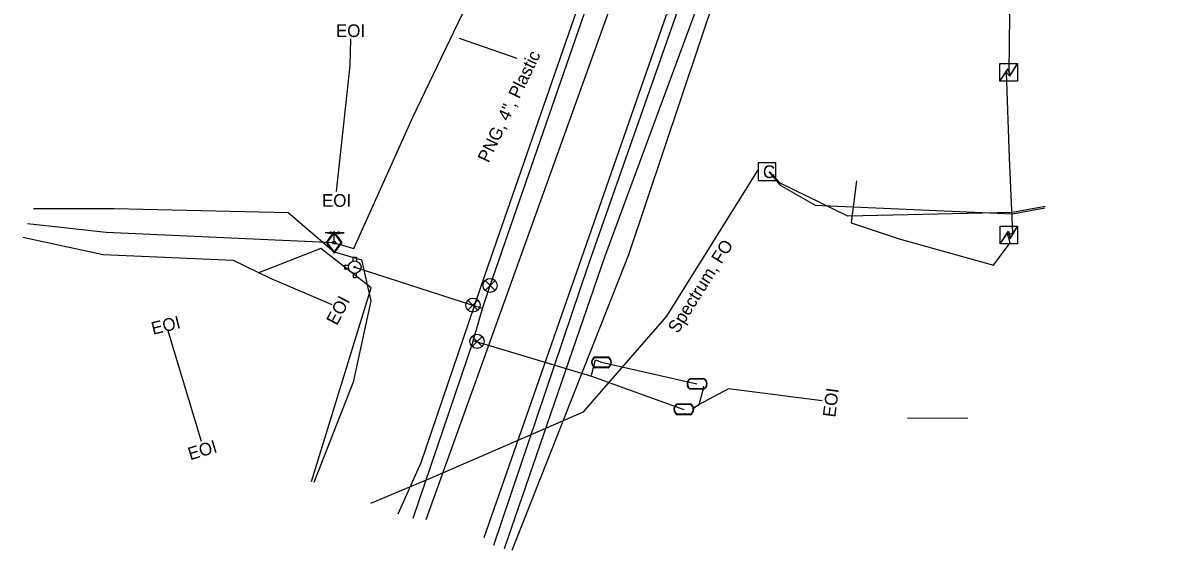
# Model space of a CAD drawing. Extents: x 2070721 to 2083039, y 729290 to 737883.
# Drawn here: x 2080826 to 2081187.2, y 732787 to 732953.4 of the extents above; entities that cross this region are included whole.
import ezdxf

# ---------------------------------------------------------------- set-up
doc = ezdxf.new("R2010")
doc.units = 0
for name, color, linetype in [('Cogo Default Point CELL', 7, 'Continuous'), ('COGO Default Point Elevation', 7, 'Continuous'), ('COGO Default Point Number', 7, 'Continuous'), ('Exist Utilities Gas UG Line SUE LOS B Cogo Point CELL', 7, 'Continuous'), ('Exist Utilities Gas Valve Cogo Number', 7, 'Continuous'), ('Exist Utilities Power UG Cable SUE LOS B Cogo Comment', 7, 'Continuous'), ('Exist Utilities Telephone UG Cable SUE LOS C Cogo Comment', 7, 'Continuous'), ('Exist Utilities Telephone UG Cable SUE LOS C Cogo Number', 7, 'Continuous'), ('Exist Utilities Telephone UG FO Cogo Point CELL', 7, 'Continuous'), ('Exist Utilities Telephone UG FO SUE LOS B Cogo Point CELL', 7, 'Continuous'), ('Exist Utilities TV Pedestal CELL', 7, 'Continuous'), ('Exist Utilities TV Pedestal Cogo Elevation', 7, 'Continuous'), ('Exist Utilities TV Pedestal Cogo Number', 7, 'Continuous'), ('Exist Utilities TV UG Cable Cogo Point CELL', 7, 'Continuous'), ('Exist Utilities TV UG Cable SUE LOS C Cogo Comment', 7, 'Continuous'), ('Exist Utilities TV UG Cable SUE LOS C Cogo Elevation', 7, 'Continuous'), ('Exist Utilities TV UG Cable SUE LOS C Cogo Number', 7, 'Continuous'), ('Exist Utilities TV UG Cable SUE LOS C Cogo Point CELL', 7, 'Continuous'), ('Exist Utilities TV UG FO Cable SUE Cogo Point CELL', 7, 'Continuous'), ('Exist Utilities TV UG FO Cable SUE LOS B Cogo Comment', 7, 'Continuous'), ('Exist Utilities TV UG FO Cable SUE LOS B Cogo Elevation', 7, 'Continuous'), ('Exist Utilities Water Meter Cogo Elevation', 7, 'Continuous')]:
    doc.layers.add(name, color=color, linetype=linetype)

msp = doc.modelspace()

# ---------------------------------------------------------------- linework, layer by layer
at = {"layer": 'Cogo Default Point CELL'}
msp.add_line((2081060.69, 732906.43), (2081060.69, 732906.43), dxfattribs=at)
msp.add_lwpolyline([(2081057.92, 732903.65), (2081063.47, 732903.65), (2081063.47, 732909.2), (2081057.92, 732909.2), (2081057.92, 732903.65)], dxfattribs=at)
at = {"layer": 'COGO Default Point Elevation'}
for points in [[(2080974.93, 732872.11), (2080971.78, 732868.96), (2080973.35, 732870.54), (2080974.93, 732868.96), (2080971.78, 732872.11)], [(2080969.51, 732865.91), (2080966.36, 732862.76), (2080967.94, 732864.33), (2080969.51, 732862.76), (2080966.36, 732865.91)], [(2080970.81, 732854.48), (2080967.66, 732851.33), (2080969.23, 732852.91), (2080970.81, 732851.33), (2080967.66, 732854.48)]]:
    msp.add_lwpolyline(points, dxfattribs=at)
for centre in [(2080973.35, 732870.54), (2080967.94, 732864.33), (2080969.23, 732852.91)]:
    msp.add_circle(centre, 2.23, dxfattribs=at)
at = {"layer": 'COGO Default Point Number'}
msp.add_line((2080930.67, 732876.3), (2080930.67, 732876.3), dxfattribs=at)
for points in [[(2080930.15, 732878.21), (2080930.15, 732879.5), (2080931.18, 732879.5), (2080931.18, 732878.18)], [(2080928.75, 732876.81), (2080927.47, 732876.81), (2080927.47, 732875.78), (2080928.75, 732875.78)], [(2080930.15, 732874.38), (2080930.15, 732873.1), (2080931.18, 732873.1), (2080931.18, 732874.41)]]:
    msp.add_lwpolyline(points, dxfattribs=at)
for radius in [1.98, 0.243]:
    msp.add_circle((2080930.67, 732876.3), radius, dxfattribs=at)
at = {"layer": 'Exist Utilities Gas Valve Cogo Number'}
msp.add_line((2080963.56, 732948.59), (2080981.81, 732942.29), dxfattribs=at)
at = {"layer": 'Exist Utilities Power UG Cable SUE LOS B Cogo Comment'}
for p, q in [((2080927.31, 732887.13), (2080921.34, 732887.13)), ((2080924.17, 732884.04), (2080924.17, 732887.13)), ((2080924.17, 732887.13), (2080927.31, 732887.13)), ((2080924.17, 732884.04), (2080924.17, 732884.04))]:
    msp.add_line(p, q, dxfattribs=at)
for points in [[(2080921.34, 732887.13), (2080923.32, 732887.47), (2080922.9, 732887.13), (2080923.28, 732886.82)], [(2080927.31, 732887.13), (2080925.34, 732886.78), (2080925.76, 732887.13), (2080925.37, 732887.43)]]:
    msp.add_lwpolyline(points, close=True, dxfattribs=at)
msp.add_circle((2080924.17, 732884.04), 0.517, dxfattribs=at)
at = {"layer": 'Exist Utilities Telephone UG Cable SUE LOS C Cogo Comment'}
for points in [[(2080929.29, 732948.39), (2080929.09, 732939.96), (2080924.86, 732900.17)], [(2080826.03, 732885.74), (2080851.32, 732880.36), (2080892.32, 732878.51), (2080903.75, 732872.9), (2080923.44, 732864.52)], [(2080882.35, 732821.33), (2080871.74, 732856.59)]]:
    msp.add_lwpolyline(points, dxfattribs=at)
at = {"layer": 'Exist Utilities Telephone UG Cable SUE LOS C Cogo Number'}
for p, q in [((2081136.91, 732937.96), (2081136.91, 732937.96)), ((2081137, 732886.66), (2081137, 732886.66))]:
    msp.add_line(p, q, dxfattribs=at)
for points in [[(2081134.06, 732940.57), (2081139.61, 732940.57), (2081139.61, 732935.02), (2081134.06, 732935.02)], [(2081134.16, 732889.27), (2081139.71, 732889.27), (2081139.71, 732883.72), (2081134.16, 732883.72)]]:
    msp.add_lwpolyline(points, close=True, dxfattribs=at)
for points in [[(2081134.06, 732935.02), (2081136.71, 732938.96), (2081137.34, 732936.75), (2081139.61, 732940.57)], [(2081134.13, 732935.02), (2081136.71, 732938.75), (2081137.29, 732936.57), (2081139.61, 732940.42)], [(2081134.16, 732883.72), (2081136.8, 732887.66), (2081137.43, 732885.45), (2081139.71, 732889.27)], [(2081134.23, 732883.72), (2081136.8, 732887.45), (2081137.39, 732885.27), (2081139.71, 732889.12)]]:
    msp.add_lwpolyline(points, dxfattribs=at)
at = {"layer": 'Exist Utilities Telephone UG FO Cogo Point CELL'}
for p, q in [((2081008.49, 732846.29), (2081008.49, 732846.29)), ((2081038.62, 732839.51), (2081038.62, 732839.51)), ((2081034.46, 732831.47), (2081034.46, 732831.47))]:
    msp.add_line(p, q, dxfattribs=at)
for points in [[(2081006.45, 732847.99), (2081010.53, 732847.99)], [(2081006.45, 732847.86), (2081010.53, 732847.86)], [(2081010.53, 732844.73), (2081006.43, 732844.73)], [(2081010.53, 732844.59), (2081006.43, 732844.59)], [(2081040.65, 732837.95), (2081036.55, 732837.95)], [(2081036.58, 732841.21), (2081040.65, 732841.21)], [(2081036.58, 732841.08), (2081040.65, 732841.08)], [(2081040.65, 732837.81), (2081036.55, 732837.81)], [(2081032.42, 732833.17), (2081036.49, 732833.17)], [(2081032.42, 732833.04), (2081036.49, 732833.04)], [(2081036.49, 732829.91), (2081032.39, 732829.91)], [(2081036.49, 732829.77), (2081032.39, 732829.77)]]:
    msp.add_lwpolyline(points, dxfattribs=at)
for centre, radius, start, end in [((2081007.18, 732846.29), 1.86, 113.178, 245.9794), ((2081007.19, 732846.29), 1.73, 115.3009, 243.7824), ((2081009.78, 732846.3), 1.86, 293.6483, 66.3084), ((2081009.79, 732846.29), 1.73, 295.1272, 64.8728), ((2081037.31, 732839.51), 1.86, 113.178, 245.9794), ((2081037.32, 732839.51), 1.73, 115.3009, 243.7824), ((2081039.91, 732839.51), 1.86, 293.6483, 66.3084), ((2081039.92, 732839.51), 1.73, 295.1272, 64.8728), ((2081033.15, 732831.47), 1.86, 113.178, 245.9794), ((2081033.16, 732831.47), 1.73, 115.3009, 243.7824), ((2081035.75, 732831.47), 1.86, 293.6483, 66.3084), ((2081035.76, 732831.47), 1.73, 295.1272, 64.8728)]:
    msp.add_arc(centre, radius, start, end, dxfattribs=at)
at = {"layer": 'Exist Utilities Telephone UG FO SUE LOS B Cogo Point CELL'}
msp.add_line((2080924.15, 732884.11), (2080924.15, 732884.11), dxfattribs=at)
msp.add_lwpolyline([(2080924.15, 732887.52), (2080921.61, 732884.11), (2080924.15, 732880.7), (2080926.69, 732884.11), (2080924.15, 732887.52)], dxfattribs=at)
msp.add_lwpolyline([(2080926.44, 732884.11), (2080924.15, 732887.19), (2080921.86, 732884.11), (2080924.15, 732881.03)], close=True, dxfattribs=at)
at = {"layer": 'Exist Utilities TV Pedestal CELL'}
for points in [[(2080935.73, 732801.82), (2080954.6, 732809.74), (2081002.83, 732830.64), (2081029.04, 732860.86), (2081058.1, 732907.32)], [(2081061.28, 732906.35), (2081064.79, 732902.23), (2081075.86, 732895.9), (2081138.1, 732893.11), (2081148.25, 732895.04)]]:
    msp.add_lwpolyline(points, dxfattribs=at)
at = {"layer": 'Exist Utilities TV Pedestal Cogo Elevation'}
msp.add_line((2080968.02, 732853.09), (2080948.97, 732796.99), dxfattribs=at)
for points in [[(2080968.02, 732853.09), (2080971.09, 732863.55), (2080973.36, 732870.49), (2081004.03, 732959.14), (2081024.87, 733018.36), (2081055.27, 733107.45), (2081086.77, 733195.01), (2081116.19, 733277.07), (2081135.71, 733336.57)], [(2080930.66, 732876.36), (2080967.82, 732864.3), (2080970.98, 732863.37)], [(2080968.03, 732853.13), (2080969.29, 732852.76), (2081005.38, 732841.9), (2081034.46, 732831.44)], [(2081005.33, 732842.26), (2081006.62, 732847.09), (2081008.47, 732846.29), (2081038.51, 732839.48)]]:
    msp.add_lwpolyline(points, dxfattribs=at)
at = {"layer": 'Exist Utilities TV Pedestal Cogo Number'}
msp.add_lwpolyline([(2080924.17, 732884.04), (2080930.33, 732882.17), (2080949.02, 732923.62), (2080986.84, 733002.49), (2081018.88, 733098.52), (2081046.79, 733177.28), (2081082.41, 733256.43), (2081124.09, 733353.56), (2081157.6, 733423.49)], dxfattribs=at)
at = {"layer": 'Exist Utilities TV UG Cable Cogo Point CELL'}
for points in [[(2080953.21, 732796.69), (2081054.09, 733077.62), (2081111.09, 733245.57), (2081176.08, 733423.78), (2081231.97, 733580.28), (2081320.16, 733847.08), (2081418.84, 734093.09), (2081467.34, 734224.03), (2081494.06, 734287.2), (2081526.74, 734352.01), (2081556, 734404.62), (2081808.13, 734757.73), (2081845.73, 734804.26), (2081874.67, 734821.58), (2081898.66, 734810.94), (2081917.15, 734795.51)], [(2080971.45, 732791.05), (2081028.93, 732955.93), (2081037.58, 732965.12), (2081059.34, 733032.5), (2081099.5, 733145.5), (2081127.24, 733222.27), (2081165.53, 733329.08), (2081197.08, 733415.76), (2081225.51, 733493.81), (2081252.34, 733568.18), (2081252.65, 733568.73)], [(2080977.85, 732787.5), (2081009.55, 732879.6), (2081045.87, 732978.13), (2081063.56, 733030.35), (2081103.18, 733143.81), (2081131.57, 733220.23), (2081172.06, 733327.38), (2081203.1, 733413.05), (2081232.13, 733491.49), (2081257.07, 733565.11), (2081257.51, 733566.68)], [(2080980.31, 732787.04), (2081017.13, 732880.26), (2081044.65, 732962.53), (2081058.02, 732999.54), (2081069.26, 733036.84), (2081073.31, 733048.09), (2081079.75, 733057.99), (2081085.51, 733069.49), (2081110.84, 733140.06), (2081139.9, 733217.95), (2081177.19, 733322.59), (2081208.97, 733410.75), (2081237.5, 733489.4), (2081264.77, 733561.01)], [(2080944.31, 732798.44), (2080951.65, 732814.71), (2080971.81, 732874.01), (2081001.7, 732960.05), (2081020.52, 733019.4), (2081051.78, 733107.87), (2081085.75, 733202.6), (2081111.57, 733279.04), (2081128.94, 733334.77), (2081148.26, 733379.04), (2081175.1, 733448.52), (2081180.53, 733478.86)]]:
    msp.add_lwpolyline(points, dxfattribs=at)
at = {"layer": 'Exist Utilities TV UG Cable SUE LOS C Cogo Comment'}
msp.add_line((2081123.97, 732828.63), (2081104.97, 732828.59), dxfattribs=at)
for points in [[(2081122.3, 732987.96), (2081131.78, 732974.98), (2081137.18, 732955.83), (2081136.91, 732937.96)], [(2081088.9, 732903.55), (2081087.25, 732890.31), (2081102.37, 732885.27), (2081132.05, 732876.97), (2081137.39, 732883.98), (2081136.65, 732886.55), (2081138.2, 732887.18), (2081137.19, 732910.83), (2081136.21, 732937.71), (2081137.11, 732936.68)], [(2080917.03, 732808.65), (2080935.8, 732869.83), (2080919.99, 732882.22), (2080900.14, 732874.41)], [(2081037.14, 732831.71), (2081039.26, 732832.94), (2081040.66, 732838.05), (2081040.66, 732838.79)], [(2081078.04, 732834.13), (2081048.56, 732837.93), (2081039.26, 732832.93), (2081037.16, 732831.49)]]:
    msp.add_lwpolyline(points, dxfattribs=at)
at = {"layer": 'Exist Utilities TV UG Cable SUE LOS C Cogo Elevation'}
msp.add_lwpolyline([(2080829.41, 732894.84), (2080854.76, 732894.84), (2080909.66, 732893.59), (2080924.17, 732881.11), (2080932.75, 732878.63), (2080935.76, 732865.71), (2080930.15, 732839.98), (2080917.79, 732808.38)], dxfattribs=at)
at = {"layer": 'Exist Utilities TV UG Cable SUE LOS C Cogo Number'}
msp.add_lwpolyline([(2081148.4, 732895.44), (2081138.13, 732893.6), (2081086.19, 732892.4), (2081064.85, 732902.78), (2081061.5, 732906.51)], dxfattribs=at)
at = {"layer": 'Exist Utilities TV UG Cable SUE LOS C Cogo Point CELL'}
msp.add_lwpolyline([(2080974.54, 732788.58), (2081004.48, 732877.32), (2081038.77, 732975.1), (2081057.5, 733033.86), (2081097.09, 733146.25), (2081124.3, 733222.73), (2081163.35, 733330.31), (2081194.31, 733416.96), (2081222.79, 733494.92), (2081247.13, 733564.12), (2081248.81, 733567.64)], dxfattribs=at)
at = {"layer": 'Exist Utilities TV UG FO Cable SUE Cogo Point CELL'}
msp.add_lwpolyline([(2080827.48, 732890.09), (2080852.24, 732887.36), (2080924.15, 732884.11)], dxfattribs=at)

# ---------------------------------------------------------------- texts
at = {"layer": 'Cogo Default Point CELL'}
msp.add_text('C', height=4, dxfattribs=at).set_placement((2081059.39, 732904.43))
at = {"layer": 'Exist Utilities Gas UG Line SUE LOS B Cogo Point CELL'}
msp.add_text('Spectrum, FO', height=4, rotation=57.9806, dxfattribs=at).set_placement((2081032.55, 732855.14))
at = {"layer": 'Exist Utilities TV UG FO Cable SUE LOS B Cogo Comment'}
msp.add_text('EOI', height=4, rotation=82.6019, dxfattribs=at).set_placement((2081082.19, 732828.78))
at = {"layer": 'Exist Utilities TV UG FO Cable SUE LOS B Cogo Elevation'}
for p in [(2080924.72, 732948.92), (2080920.32, 732895.36)]:
    msp.add_text('EOI', height=4, dxfattribs=at).set_placement(p)
for rotation, p in [(62.1978, (2080925.03, 732857.69)), (13.7971, (2080867.07, 732854.94)), (16.7177, (2080878.77, 732815.37))]:
    msp.add_text('EOI', height=4, rotation=rotation, dxfattribs=at).set_placement(p)
at = {"layer": 'Exist Utilities Water Meter Cogo Elevation'}
msp.add_text('PNG, 4", Plastic', height=4, rotation=64.3748, dxfattribs=at).set_placement((2080972.85, 732908.99))

doc.saveas('drawing.dxf')
